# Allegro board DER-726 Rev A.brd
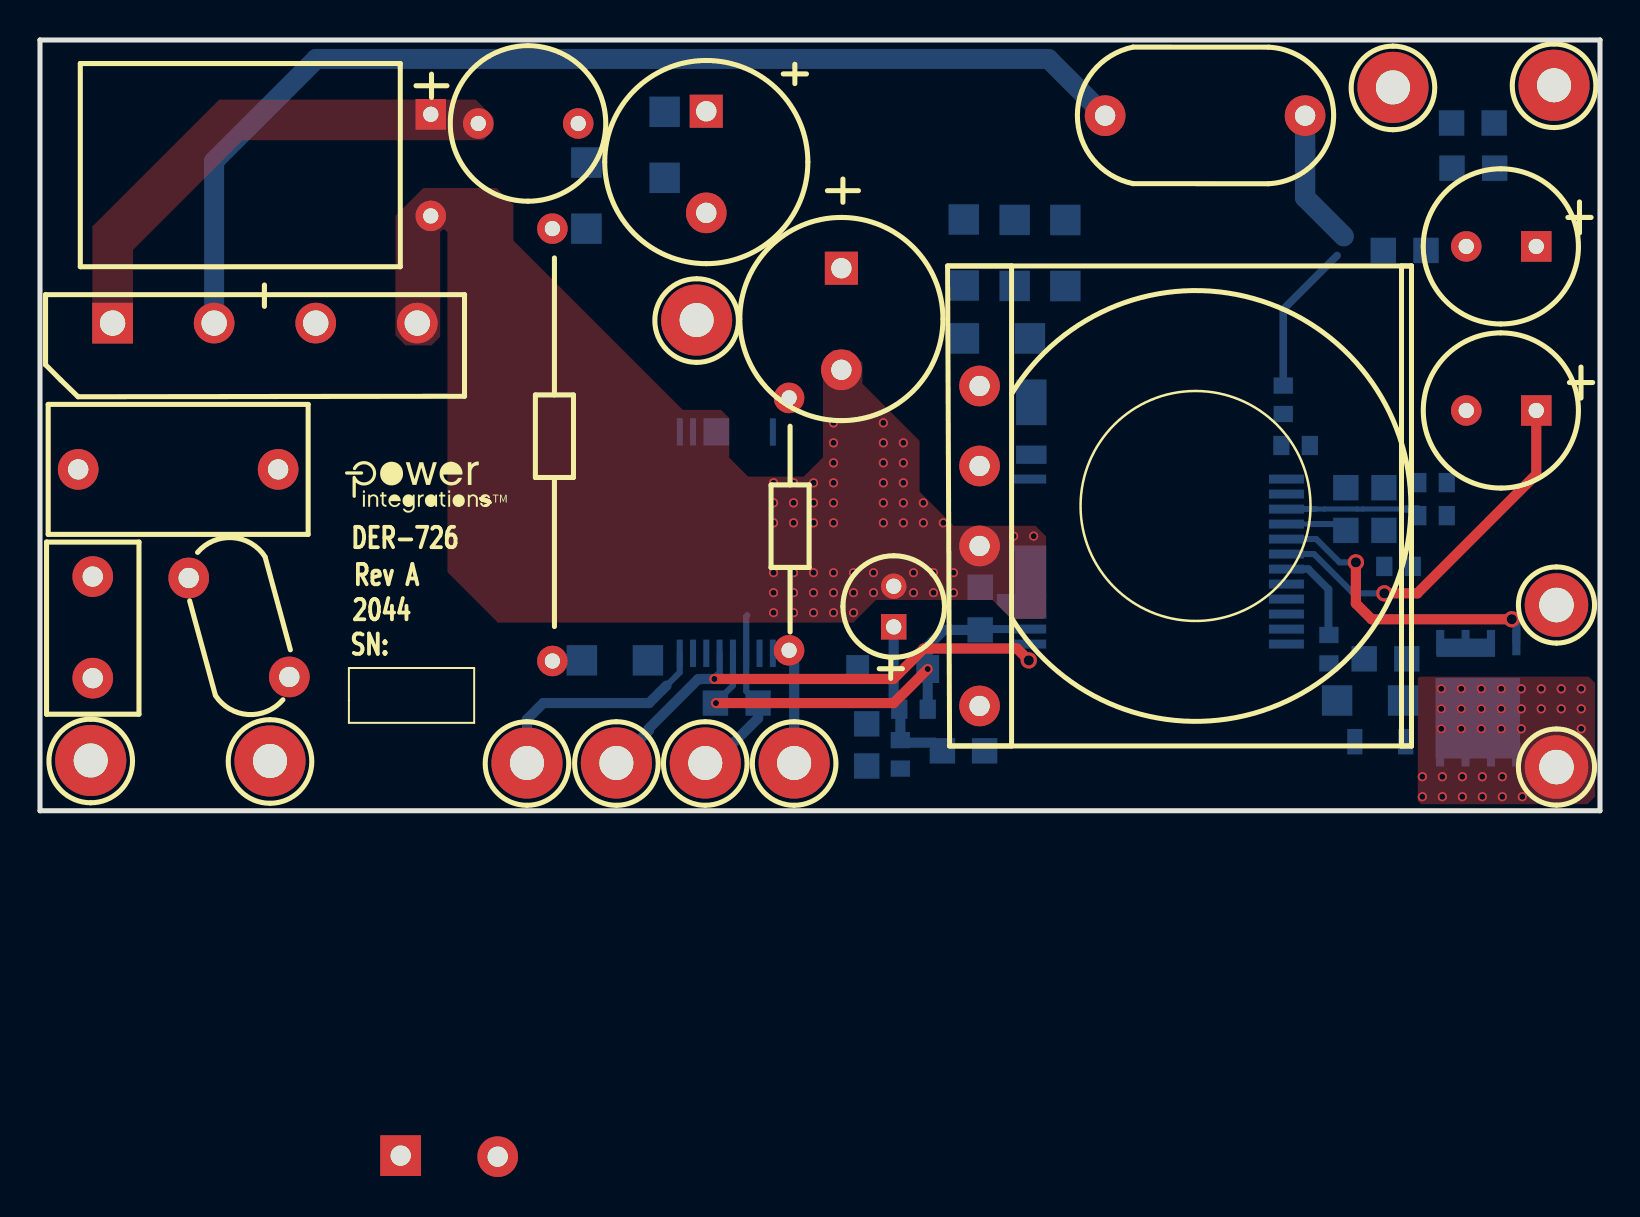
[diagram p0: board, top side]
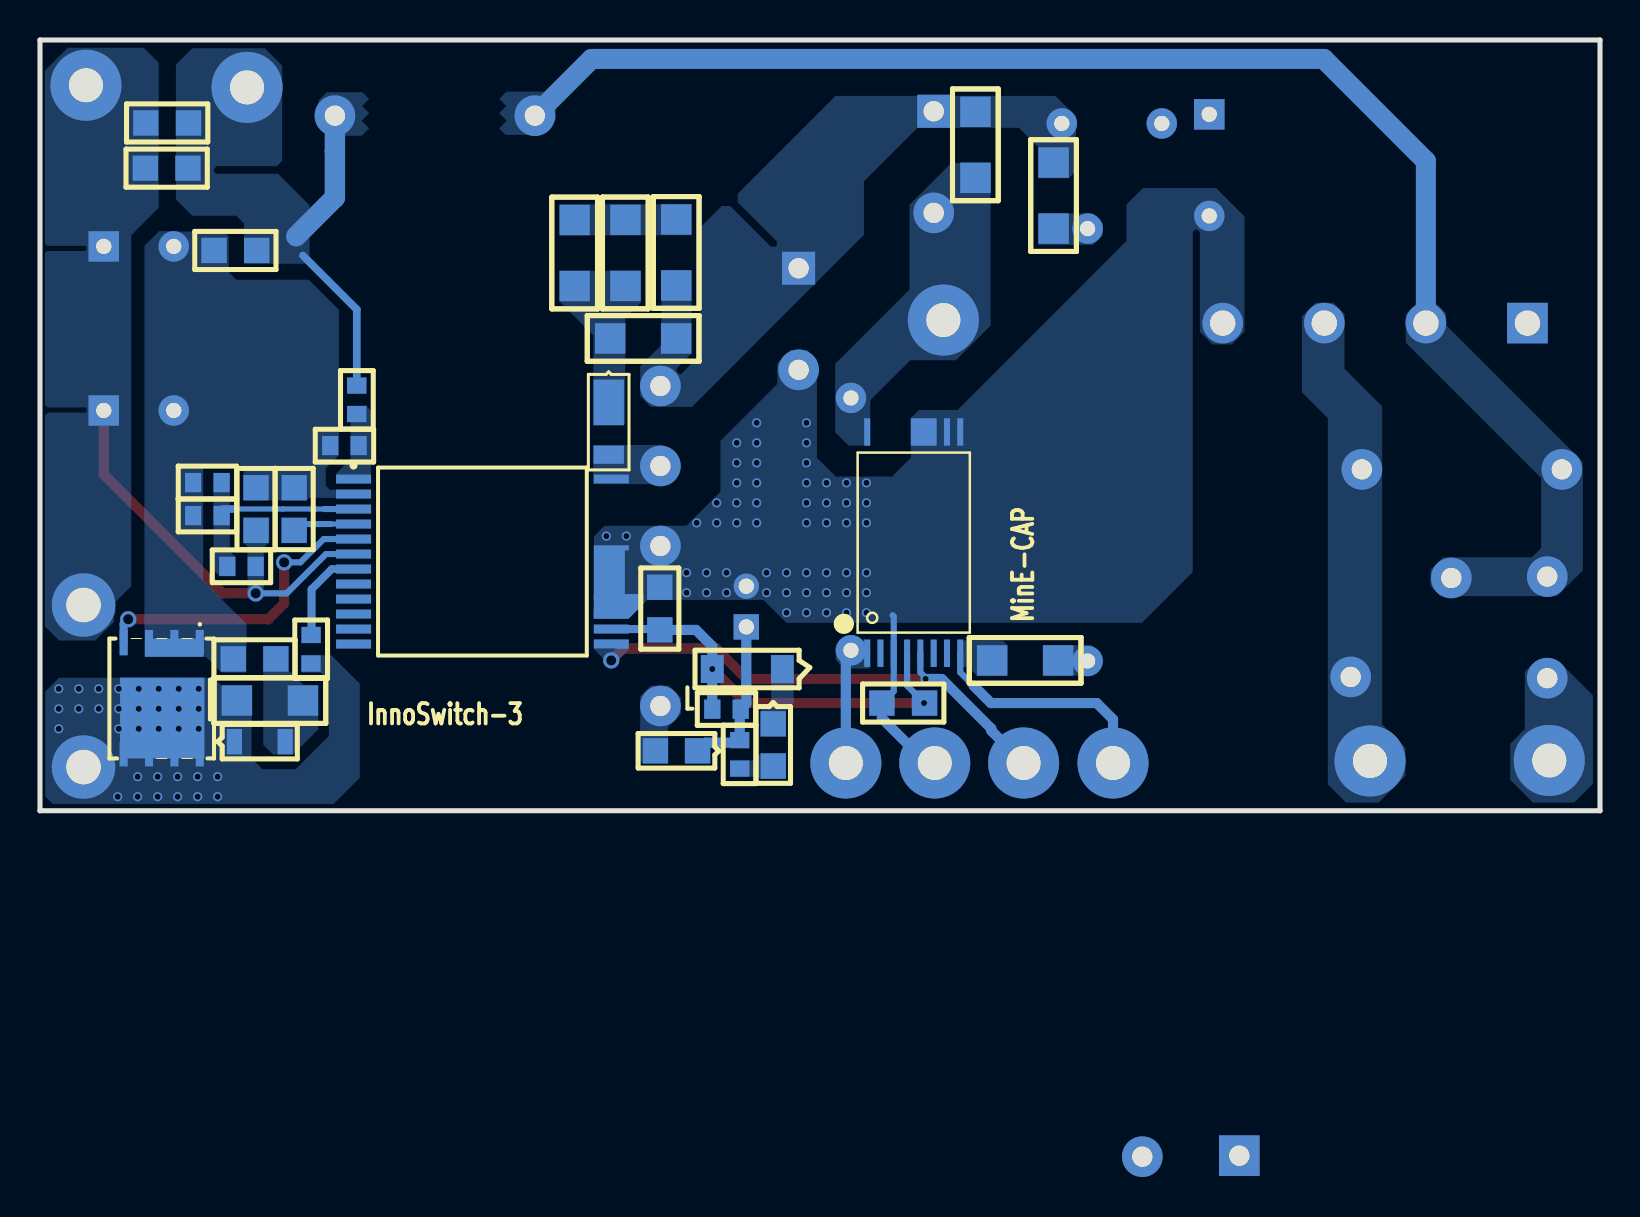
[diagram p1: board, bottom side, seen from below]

Outline 78.02 x 38.54 mm; copper layers: TOP, BOTTOM. Coordinates in mm from the lower left corner of the outline.
Outline path: 0,38.54 78.02,38.54 78.02,0 0,0 0,38.54

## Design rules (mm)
constraint set DEFAULT: min track width 0.508

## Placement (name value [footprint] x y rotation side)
BR1  GBL06  [PIDAXBRIDGEGBL06]  3.63 24.38 0 top
C1  0.1 uF  [PINPXCAPRAD13X7LS10MMD040]  11.91 17.07 180 top
C2  18 uf  [PIPOLCAPCYLD400LS200040]  19.54 34.82 270 top
C3  68 uF  [PIPOLCAPCYLD400LS200040]  33.32 34.98 270 top
C4  33 nF  [PISMC0805]  35.91 5.38 180 bottom
C5  18 uf  [PIPOLCAPCYLD400LS200040]  40.08 27.13 270 top
C6  1000 pF  [PISMC1206]  46.2 26.26 90 bottom
C7  33 uF  [PIPOLCAPCLYD200LS80030]  42.69 9.19 90 top
C8  4.7 uF  [PISMC0805]  47.02 9.04 90 bottom
C9  470 pF  [PINPCAPRAD374X275LS394D040]  53.27 34.76 0 top
C10  1 nF  [PISMC0805]  66.22 7.59 0 bottom
C11  2.2 uF  [PISMC0805]  65.31 16.15 270 bottom
C12  330 uF  [PIPOLCAPCYLD315LS138D030]  74.83 20.02 180 top
C13  1 uF  [PISMC0805]  67.21 16.15 270 bottom
C14  330 uF  [PIPOLCAPCYLD315LS138D030]  74.83 28.22 180 top
C15  330 pF  [PISMC0603]  63.5 18.26 180 bottom
C16  330 pF  [PISMC0603]  68.93 16.41 0 bottom
C18  4.7 uF  [PISMC0805]  72.73 34.39 180 bottom
C19  4.7 uF  [PISMC0805]  72.75 32.13 180 bottom
D  RED  [PITPKEYSTONE125X125]  32.84 24.54 0 top
D1  BAS416,115  [PISMDSOD323]  41.35 4.34 270 bottom
D2  DFLR1800-7  [PISMDDFLR120012]  49.58 20.45 90 bottom
D3  BAV20WS-7-F  [PISMDSOD323]  45.13 3 0 bottom
D4  BAV19WS  [PISMSOD323]  68.3 3.45 180 bottom
F1  3.15 A  [PI_RST_MICROFUSE]  2.64 6.63 90 top
FL1  Hole_70mils  [PI_HOLE_70MIL]  75.84 2.16 0 top
FL2  Hole_70mils  [PI_HOLE_70MIL]  75.84 10.26 0 top
GND  BLK  [PITPKEYSTONE125X125]  67.66 36.17 0 top
L  BLK  [PITPKEYSTONE125X125]  2.54 2.51 0 top
L3  47 uH  [PICHOKETOKINVD345H453LS197D030]  21.92 34.37 0 top
N  WHT  [PITPKEYSTONE125X125]  11.5 2.49 0 top
NOREF  -  []  0 0 90 top
NOREF#2  -  []  -231.6 -144.78 0 top
NOREF#3  -  []  14.7 17.37 0 top
NOREF#4  -  []  0 38.54 0 top
NOREF#5  -  []  -153.78 54.23 0 top
Q1  AONS62922  [PISMPQFN5X6B]  70.03 8.41 0 bottom
R1  3.9 M  [PISMR1206]  31.24 34.95 270 bottom
R2  1 M  [PI18WVRESD80LS100D030]  37.46 20.14 270 top
R3  1.8 M  [PISMR1206]  27.33 32.41 270 bottom
R4  1 M  [PI18WVRESD80LS100D030#2]  25.63 29.11 270 top
R5  1 M  [PISMR1206]  27.1 7.52 0 bottom
R6  3 k  [PISMR0603]  42.97 5.08 0 bottom
R7  47  [PISMR1206]  51.28 29.54 270 bottom
R8  47  [PISMR1206]  48.74 29.54 270 bottom
R9  47  [PISMR0603]  43.02 3.53 270 bottom
R10  390 k  [PISMR1206]  46.2 23.62 0 bottom
R11  47  [PISMR0603]  64.46 7.37 90 bottom
R12  10  [PISMR1206]  68.17 5.51 180 bottom
R13  0.0  [PISMR0603]  62.18 19.84 90 bottom
R14  169 k  [PISMR0603]  67.23 12.22 0 bottom
R15  11.5 k  [PISMR0603]  68.93 14.76 0 bottom
R16  0.009  [PISMR0805]  69.31 28.02 180 bottom
RV1  275 Vac  [PIDISC350X160LS210X140040]  10.87 12.57 285.2 top
S  BLK  [PITPKEYSTONE125X125]  33.27 2.39 0 top
T1  EQ25  [PI_BOBBIN_EQ-25_6P]  57.79 15.24 0 top
U1  MIN1072M  [PI_SM_MINSOP16A_1]  36.65 7.87 180 bottom
U2  INN3679C-H606  [PI_IC_INSOP_24D]  62.34 16.59 180 bottom
V  BLU  [PITPKEYSTONE125X125]  28.83 2.39 0 top
VBOT  WHT  [PITPKEYSTONE125X125]  37.72 2.39 0 top
VO  RED  [PITPKEYSTONE125X125]  75.72 36.28 0 top
VR1  MMSZ5248B-7-F  [PI_SM_SOD-123_12]  40.89 7.09 0 bottom
VTOP  YEL  [PITPKEYSTONE125X125]  24.36 2.39 0 top

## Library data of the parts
BR1 = DISCRETE BRIDGE_+~~-
C1 = CAP NP: alternate symbols: (pinpxcaprad13x7LS10mmD040H)
C2 C5 = CAP POL: alternate symbols: (pipolcapclyd395x630ls200030h)
C3 = CAP POL: alternate symbols: (pipolcapcyld10x20x5mmlsd30h)
C4 C6 C8 C9 C11 C15 C16 C18 C19 = CAP NP
C7 = CAP POL: alternate symbols: (pipolcapclyd200ls80030h)
C10 = CAP NP: alternate symbols: (pismc0805_1); room: 2
C12 C14 = CAP POL: alternate symbols: (pipolcapcyld315ls138d030h); room: 2
C13 = CAP NP: room: 2
D GND L N S V VBOT VO VTOP = TESTPOINT
D1 D3 = DIODE
D2 = DIODE: room: 1
D4 = DIODE: room: 2
F1 = FUSE: alternate symbols: (pirstmicrofusehoz); room: 1
FL1 FL2 = FlyingLead: room: 2
L3 = INDUCTOR: alternate symbols: (pichoketokinvd345h453ls197d030H)
Q1 = FET_N_SGD_123_4_5678: room: 2
R1 R3 R5-R8 R10 R12-R16 = R
R2 R4 = R: alternate symbols: (pi18wresd080ls300d030)
R9 = R: alternate symbols: (pismr0603_1); room: 1
R11 = R: alternate symbols: (pismr0603_1); room: 2
RV1 = VARISTOR: alternate symbols: (pi_disc_354x220_ls220x10_040_h); room: 1
T1 = BEQ25_6P
U1 = MinE-CAP
U2 = Inno3EP_P15
VR1 = DIODE_ZENER

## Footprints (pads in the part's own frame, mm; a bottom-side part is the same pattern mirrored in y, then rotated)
PI18WVRESD80LS100D030
  round 1.524 hole 0.762: 1(-0.5,0) 2(12.12,0)
PI18WVRESD80LS100D030#2
  round 1.524 hole 0.762: 1(0,0) 2(21.62,0)
PI_BOBBIN_EQ-25_6P
  rect 2.032x2.032 hole 1.016: 1(-39.751,-32.487)
  round 2.032 hole 1.016: 2(-10.8,6) 3(-10.8,2) 4(-10.8,-2) 5(-34.9,-32.537) 6(-10.8,-10)
PI_HOLE_70MIL
  round 3.175 hole 1.727: 1(0,0.025)
PI_IC_INSOP_24D
  rect 1.75x0.45 smd: 1(0,0) 2(0,-0.75) 3(0,-1.5) 4(0,-2.25) 5(0,-3) 6(0,-3.75) 7(0,-4.5) 8(0,-5.25) 9(0,-6) 10(0,-6.75) 11(0,-7.5) 12(0,-8.25) 13(12.89,-8.25) 14(12.89,-7.5) 15(12.89,-6.75) 24(12.89,0)
  custom 0.438x0.438 smd: 16(12.89,-4.67)
PI_RST_MICROFUSE
  round 2.032 hole 1.016: 1(0,0) 2(5.08,0)
PI_SM_MINSOP16A_1
  rect 0.3x1.37 smd: 1(0,0) 2(0.665,0) 3(1.33,0) 4(1.995,0) 5(2.66,0) 6(3.325,0) 7(3.99,0) 8(4.655,0) 9(4.655,11.067) 10(3.99,11.067) 16(0,11.067)
  rect 1.292x1.37 smd: 11(2.829,11.067)
PI_SM_SOD-123_12
  rect 1.143x1.397 smd: 1(0,0) 2(3.505,0)
PICHOKETOKINVD345H453LS197D030
  round 1.524 hole 0.762: 1(0,0) 2(5,0)
PIDAXBRIDGEGBL06
  rect 2.032x2.032 hole 1.27: 1(0,0)
  round 2.032 hole 1.27: 2(5.08,0) 3(10.16,0) 4(15.24,0)
PIDISC350X160LS210X140040
  round 2.032 hole 1.016: 1(0,-3.556) 2(6.096,0)
PINPCAPRAD374X275LS394D040
  round 2.032 hole 1.016: 1(0,0) 2(10,0)
PINPXCAPRAD13X7LS10MMD040
  round 2.032 hole 1.016: 1(0,0) 2(10,0)
PIPOLCAPCLYD200LS80030
  rect 1.27x1.27 hole 0.762: 1(0,0)
  round 1.27 hole 0.762: 2(2.032,0)
PIPOLCAPCYLD315LS138D030
  rect 1.524x1.524 hole 0.762: 1(0,0)
  round 1.524 hole 0.762: 2(3.5,0)
PIPOLCAPCYLD400LS200040
  rect 1.651x1.651 hole 1.016: 1(0,0)
  round 2.032 hole 1.016: 2(5.08,0)
PISMC0603
  rect 0.813x0.965 smd: 1(0,0) 2(1.422,0)
PISMC0805
  rect 1.27x1.27 smd: 1(0,0) 2(2.134,0)
PISMC1206
  rect 1.524x1.524 smd: 1(0,0) 2(3.302,0)
PISMDDFLR120012
  rect 2.286x1.524 smd: 1(-0.025,0)
  rect 0.914x1.524 smd: 2(-2.642,0)
PISMDSOD323
  rect 1.27x1.27 smd: 1(0,0) 2(2.108,0)
PISMPQFN5X6B
  rect 0.406x1.27 smd: 1(0,0) 2(1.27,0) 3(2.54,0) 4(3.81,0)
  rect 0.406x1.219 smd: 5(3.81,5.588) 6(2.54,5.588) 7(1.27,5.588) 8(0,5.588)
PISMR0603
  rect 0.813x0.965 smd: 1(0,0) 2(1.422,0)
PISMR0805
  rect 1.27x1.27 smd: 1(0,0) 2(2.134,0)
PISMR1206
  rect 1.524x1.524 smd: 1(0,0) 2(3.302,0)
PISMSOD323
  rect 0.762x1.27 smd: 1(0,0) 2(2.54,0)
PITPKEYSTONE125X125
  round 3.556 hole 1.702: 1(0,0)

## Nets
D: D4.1 FL1.1 Q1.5 Q1.6 Q1.7 Q1.8 R11.1 R12.1
NC8: U2.8
NC9: U2.9
NC10: U2.10
NC11: U2.11
NC12: U2.12
S: C10.2 C11.1 C12.2 C13.1 C14.2 C15.1 C16.2 Q1.1(S) Q1.2 Q1.3 R15.2 R16.1 U2.2
N11525368: BR1.2 C1.2 C9.1 F1.2 RV1.1
N11525664: BR1.3(AC2) C1.1 N.1 RV1.2
N11525782: C3.1 C5.1 C6.1 L3.2 R1.1 R3.1 R10.1 T1.2
N11525810: C9.2 C18.2 C19.2 GND.1 R13.2 R16.2
N11525884: C6.2 R7.1 R8.1
N11526002: D2.1 R7.2 R8.2 R10.2
N11526006: C12.1 C13.2 C14.1 C18.1 C19.1 FL2.1 R14.1 U2.6 VO.1
N11526148: D2.2 T1.3 U2.24
N11526230: BR1.4 C2.2 C4.1 C5.2 C7.2 C8.2 S.1 T1.4 U1.3 U1.9 U1.10 U1.11 U2.16
N11526330: C16.1 R14.2 R15.1 U2.3
N11526430: D3.2 T1.6
N11526456: C10.1 D4.2 R12.2
N11526718: Q1.4 U2.5
N11526838: C7.1 D3.1 R6.1 R9.1
N11527062: D1.2 R9.2
N11527294: C15.2 R13.1 U2.1
N11527492: C4.2 C8.1 R6.2 U1.4 U2.14 VR1.2
N11532941: R3.2 R4.1
N11533086: C3.2 D.1 R1.2 R2.1 U1.16
N11543266: R4.2 R5.1
N11556072: R5.2 U1.8 VTOP.1
N11567872: U1.5 U2.13(VPIN) V.1
N11568750: BR1.1 C2.1 L3.1
N12363198: R2.2 U1.1 VBOT.1
N12366027: C11.2 U2.4
N12367034: F1.1 L.1
N12372611: D1.1 VR1.1
N12385908: R11.2 U2.7

Pads without a net: T1 1 5; U1 2 6 7; U2 15

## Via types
v1: diameter 0.813, hole 0.508, TOP to BOTTOM, 4 vias
v2: diameter 0.457, hole 0.305, TOP to BOTTOM, 90 vias

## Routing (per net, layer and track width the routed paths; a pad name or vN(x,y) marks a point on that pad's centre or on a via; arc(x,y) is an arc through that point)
D:
  vias: v2(69.13,1.7) v2(69.13,0.7) v2(70.08,6.1) v2(70.08,5.1) v2(70.08,4.1) v2(70.13,1.7) v2(70.13,0.7) v2(71.08,6.1) v2(71.08,5.1) v2(71.08,4.1) v2(71.13,1.7) v2(71.13,0.7) v2(72.08,6.1) v2(72.08,5.1) v2(72.08,4.1) v2(72.13,1.7) v2(72.13,0.7) v2(73.08,6.1) v2(73.08,5.1) v2(73.08,4.1) v2(73.13,1.7) v2(73.13,0.7) v2(74.08,6.1) v2(74.08,5.1) v2(74.08,4.1) v2(74.13,0.7) v2(75.08,6.1) v2(75.08,5.1) v2(76.08,6.1) v2(76.08,5.1) v2(77.08,6.1) v2(77.08,5.1) v2(77.08,4.1)
N11525368: length 56
  BOTTOM w1: C9.1 50.43,37.59 13.81,37.59 8.71,32.49 BR1.2
N11525810: length 14.4
  BOTTOM w0.381: R13.2 62.18,25.07 64.87,27.76
  BOTTOM w1.016: C9.2 63.27,32.98 63.27,32.98 63.27,30.66 65.2,28.73
N11526006: length 19
  TOP w0.508: v1(67.23,10.87) 68.88,10.87 74.83,16.82 C12.1
  BOTTOM w0.305: U2.6 63.71,12.84 65.68,10.87 v1(67.23,10.87)
N11526230: length 9
  BOTTOM w0.305: C4.1 35.32,5.98 U1.3 35.32,9.72 35.38,9.78
  BOTTOM w0.508: C4.1 35.91,4.62 33.68,2.39 S.1
  vias: v2(36.69,16.4) v2(36.69,15.4) v2(36.69,14.4) v2(36.69,11.9) v2(36.69,10.9) v2(36.69,9.9) v2(37.69,16.4) v2(37.69,15.4) v2(37.69,14.4) v2(37.69,11.9) v2(37.69,10.9) v2(37.69,9.9) v2(38.69,16.4) v2(38.69,15.4) v2(38.69,14.4) v2(38.69,11.9) v2(38.69,10.9) v2(38.69,9.9) v2(39.69,19.4) v2(39.69,18.4) v2(39.69,17.4) v2(39.69,16.4) v2(39.69,15.4) v2(39.69,14.4) v2(39.69,11.9) v2(39.69,10.9) v2(39.69,9.9) v2(40.69,11.9) v2(40.69,10.9) v2(40.69,9.9) v2(41.69,11.9) v2(41.69,10.9) v2(42.18,19.4) v2(42.18,18.4) v2(42.18,17.4) v2(42.18,16.4) v2(42.18,15.4) v2(42.18,14.4) v2(43.18,18.4) v2(43.18,17.4) v2(43.18,16.4) v2(43.18,15.4) v2(43.18,14.4) v2(43.69,11.9) v2(43.69,10.9) v2(44.18,15.4) v2(44.18,14.4) v2(44.69,11.9) v2(44.69,10.9) v2(45.18,14.4) v2(45.69,11.9) v2(45.69,10.9) v2(48.69,13.73) v2(49.69,13.73)
N11526330: length 6.6
  BOTTOM w0.254: 68.33,15.09 66.14,15.09 66.14,15.09 65.87,15.09 65.87,15.09 64.24,15.09 64.24,15.09 63.77,15.09
  BOTTOM w0.305: 63.77,15.09 U2.3
  BOTTOM w0.381: 68.91,15.09 68.33,15.09
N11526718: length 15.4
  TOP w0.508: v1(65.81,12.42) 65.81,10.36 66.6,9.58 v1(73.61,9.58)
  BOTTOM w0.305: U2.5 63.83,13.59 64.99,12.42 v1(65.81,12.42)
  BOTTOM w0.4: Q1.4 73.84,9.35 v1(73.61,9.58)
N11526838: length 8.1
  BOTTOM w0.508: D3.1 44.73,3.4 43.15,3.4 R9.1 43.02,5.03 R6.1 42.69,5.36 C7.1
N11527492: length 22.7
  TOP w0.508: v2(33.8,5.38) 42.69,5.38 v2(44.4,7.09)
  BOTTOM w0.305: v2(33.8,5.38) C4.2 34.65,6.26 U1.4
  BOTTOM w0.4: U2.14 47.06,9.09 C8.1
  BOTTOM w0.508: R6.2 v2(44.4,7.09) 44.4,8.23 45.21,9.04 C8.1
N11556072: length 11.8
  BOTTOM w0.305: U1.8 31.99,6.92 31.33,6.26
  BOTTOM w0.508: 31.33,6.26 30.46,5.38 25.17,5.38 24.36,4.57 VTOP.1
N11567872: length 24.7
  TOP w0.508: v2(33.73,6.59) 42.68,6.59 44.2,8.11 48.86,8.11 v1(49.45,7.52)
  BOTTOM w0.305: U1.5 33.99,6.92 33.73,6.65 v2(33.73,6.59)
  BOTTOM w0.508: V.1 30.44,4 30.44,4.11 32.91,6.58 33.02,6.58 33.03,6.59 v2(33.73,6.59)
N12363198: length 5.6
  BOTTOM w0.508: VBOT.1 37.72,7.62 37.46,7.87
N12366027: length 3.1
  BOTTOM w0.254: U2.4 63.48,14.34
  BOTTOM w0.305: 63.48,14.34 64.99,14.34 C11.2
N12385908: length 4.8
  BOTTOM w0.381: U2.7 63.43,12.09 64.44,11.07
  BOTTOM w0.4: R11.2 64.44,8.81 64.44,11.07

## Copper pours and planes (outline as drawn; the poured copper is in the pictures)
D on BOTTOM (solid shape): 74.01,2.62 69.8,2.62 69.8,6.65 74.01,6.65
D on TOP: 69.06,0.33 77.39,0.33 77.77,0.71 77.77,6.4 77.47,6.71 68.98,6.71 68.91,6.63 68.91,0.48
D on BOTTOM: 77.75,0.71 77.75,5.97 77.06,6.65 69.34,6.65 68.91,6.22 67.43,6.22 67.43,2.62 66.9,2.08 65.22,2.08 63.57,3.73 63.57,6.5 63.98,6.91 64.92,6.91 64.95,6.93 64.95,7.75 64.92,7.77 63.45,7.77 62.02,6.35 62.02,1.65 63.33,0.34 77.38,0.34
S on BOTTOM (solid shape): 72.77,7.7 69.85,7.7 69.85,8.61 72.77,8.61
S on BOTTOM: 63.07,17.78 63.73,17.12 63.73,16.26 63.53,16.05 61.47,16.05 61.47,15.65 64.54,15.65 64.67,15.52 67.84,15.52 67.84,17.12 68.09,17.37 69.64,17.37 69.86,17.16 69.86,11.51 67.69,9.34 67.69,6.91 68.93,6.91 69.72,7.7 72.79,7.7 72.79,28.24 72.06,28.98 71.16,28.98 71.14,28.96 68.83,28.96 68.58,28.7 68.58,26.92 68.21,26.56 64.58,26.56 63.07,25.05
N11525368 on BOTTOM: 52.86,35.96 54.68,35.96 55.05,35.6 54.7,35.24 55.05,34.88 54.67,34.5 55.05,34.12 54.72,33.79 52.97,33.79 52.22,34.54 52.22,35.33 52.84,35.95
N11525368 on BOTTOM: 8.48,12.04 7.85,12.67 3.4,12.67 2.94,13.13 2.94,16.64 9.71,23.41 9.71,24.83 9.17,25.37 8.2,25.37 7.69,24.87 7.69,24.28 0.86,17.45 0.86,12.01 2.14,10.73 7.99,10.73 8.48,11.23
N11525664 on BOTTOM: 13.61,19.63 14.91,20.93 14.91,24.71 14.22,25.4 13.33,25.4 12.77,24.84 12.77,22.1 10.89,20.22 10.89,4.32 9.73,3.15 9.73,1.75 11.07,0.41 12.7,0.41 13.61,1.32
N11525782 on BOTTOM: 46.91,27.03 46.94,27 46.94,23.29 48,22.23 48,20.73 47.47,20.19 45.41,20.19 36.81,28.79 36.81,31.47 34.13,34.15 29.07,34.15 28.09,33.17 28.09,31.62 26.57,31.62 26.21,31.98 26.21,34.72 27.23,35.74 38.23,35.74 43.13,30.85 43.13,30.43 41.17,28.47 41.17,28.27 41.23,28.21 41.46,28.21 43.49,30.24 43.93,30.24 44.98,29.18 44.98,22.81 45.95,21.84 46.05,21.84 46.17,21.97 46.17,22.12 45.44,22.86 45.44,27.03
N11525810 on BOTTOM: 69.31,31.95 69.31,32.11 69.19,32.23 66.16,32.23 65.91,32.49 65.91,37.26 66.77,38.13 70.41,38.13 71.22,37.31 71.22,30.57 70.41,29.75 68.21,29.75 67.82,29.36 67.82,27.38 67.79,27.36 64.74,27.36 64.54,27.56 64.54,30.28 66.11,31.85 69.21,31.85
N11525810 on BOTTOM: 63.63,33.75 61.92,33.75 61.55,34.12 61.94,34.5 61.55,34.88 61.91,35.24 61.55,35.6 61.88,35.93 63.67,35.93 64.09,35.5 64.09,34.21 64.09,34.21
N11525884 on BOTTOM: 45.42,30.33 45.42,28.78 52.02,28.78 52.02,30.33
N11526002 on BOTTOM: 48.82,19.28 50.34,19.28 50.34,23.77 52.02,25.45 52.02,27 47.96,27 47.96,25.43 48.74,24.64 48.74,19.35
N11526006 on BOTTOM: 72.82,38.15 76.63,38.15 77.77,37.01 77.77,28.37 77.65,28.24 75.77,28.24 75.69,28.17 75.69,28.07 75.77,27.99 77.67,27.99 77.77,27.89 77.77,20.29 77.65,20.17 75.74,20.17 75.69,20.12 75.69,19.96 75.74,19.91 77.62,19.91 77.77,19.76 77.77,9.22 77.06,8.51 75.26,8.51 74.24,9.53 74.24,10.44 73.45,11.23 73.45,28.78 72.08,30.15 72.08,37.41
N11526006 on BOTTOM: 67.84,14.66 67.84,13.41 67.64,13.21 67.64,10.72 67.38,10.46 67.05,10.46 66.82,10.69 66.82,13.16 66.55,13.44 66.55,14.66
N11526148 on BOTTOM: 50.35,18.29 46.89,18.29 46.33,17.73 46.33,16.84 46.82,16.36 46.82,16.33 50.35,16.33
N11526230 on BOTTOM (solid shape): 50.32,9.61 48.57,9.61 47.85,10.33 47.85,10.83 50.32,10.83
N11526230 on TOP: 45.69,14.25 49.78,14.25 50.31,13.72 50.31,9.73 50.19,9.6 48.56,9.6 47.62,10.54 41.81,10.54 40.66,9.4 22.91,9.4 20.37,11.94 20.37,28.93 20.24,29.06 20.14,29.06 20.01,28.93 20.01,23.7 19.58,23.27 18.29,23.27 17.78,23.77 17.78,29.74 19.17,31.14 22.83,31.14 23.67,30.3 23.67,28.52 32.15,20.04 34.06,20.04 34.47,19.63 34.47,17.65 35.4,16.71 38.2,16.71 39.16,17.68 39.16,22.56 39.65,23.04 40.48,23.04 41.13,22.39 41.13,21.35 43.99,18.49 43.99,15.95
N11526230 on BOTTOM: 45.69,14.25 43.99,15.95 43.99,18.49 41.15,21.34 41.15,22.38 40.48,23.04 39.65,23.04 39.16,22.56 39.16,17.65 38.22,16.71 35.4,16.71 34.47,17.65 34.47,19.63 34.06,20.04 32.13,20.04 23.68,28.49 23.68,30.31 22.86,31.14 19.2,31.14 17.78,29.72 17.78,23.95 18.41,23.32 19.38,23.32 20.01,23.95 20.01,28.93 20.14,29.06 20.24,29.06 20.37,28.93 20.37,11.94 22.91,9.4 40.69,9.4 41.83,10.54 47.65,10.54 47.88,10.31 50.11,10.31 50.31,10.52 50.31,13.72 49.78,14.25
N11526330 on BOTTOM: 68.53,16.89 68.53,12.98 68.25,12.7 68.25,11.73 69.03,11.73 69.34,12.04 69.34,16.89
N11526430 on BOTTOM: 46.56,6.25 47.47,6.25 48,5.71 48,2.49 47.88,2.36 46.61,2.36 46.61,4.19 45.97,4.83 45.97,5.66
N11526456 on BOTTOM: 66.85,8.23 65.66,8.23 65.58,8.15 65.58,7.01 65.5,6.93 65.48,6.93 64.82,6.27 64.11,6.27 64.11,4.06 65.35,2.82 66.37,2.82 66.85,3.3
N11527062 on BOTTOM: 40.71,2.87 40.71,1.6 41.98,1.6 42.09,1.7 43.51,1.7 43.51,2.51 42.34,2.51 41.98,2.87
N11527294 on BOTTOM: 61.47,16.36 63.15,16.36 63.2,16.41 63.2,16.87 62.61,17.45 62.61,17.48 62.48,17.61 62.48,20.24 61.69,20.24 61.47,20.02
N11532941 on BOTTOM: 24.86,29.39 24.86,28.78 25.35,28.3 28.09,28.3 28.09,29.87 25.35,29.87
N11533086 on BOTTOM: 38.25,22.35 38.25,18.92 37.59,18.26 36.5,18.26 36.5,20.52 34.49,22.53 32.2,22.53 30.48,24.26 30.48,32.38 32.45,32.38 34.53,30.3 34.53,26.07
N11543266 on BOTTOM: 27.86,8.28 27.86,6.76 25.42,6.76 24.91,7.26 24.91,7.75 25.45,8.28
N11556072 on BOTTOM: 32.08,8.51 32.08,7.19 31.59,7.19 31.16,6.76 29.64,6.76 29.64,8.28 29.87,8.51
N11567872 on BOTTOM: 48.59,8.56 50.31,8.56 50.31,8.08 49.63,7.39 49.25,7.39 48.59,8.05
N11568750 on TOP: 4.65,28.04 10.13,33.53 22.17,33.53 22.68,34.04 22.68,34.67 21.79,35.56 8.96,35.56 2.61,29.21 2.61,23.37 4.65,23.37
N12363198 on BOTTOM: 36.5,8.56 36.5,7.19 36.57,7.11 37.79,7.11 38.22,7.54 38.22,8.2 37.87,8.56
N12367034 on BOTTOM: 3.76,6.96 3.76,4.09 4.49,3.35 4.49,1.55 3.35,0.41 1.29,0.41 0.35,1.35 0.35,5.77 2.05,7.47 3.25,7.47
N12372611 on BOTTOM: 40.71,3.71 41.98,3.71 41.98,4.98 41.45,5.51 41.45,7.77 40.33,7.77 40.33,5.41 40.71,5.03

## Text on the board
Ref Des/Silkscreen Bottom: InnoSwitch-3 | MinE-CAP
Ref Des/Silkscreen Top: SN: | DER-726 | 2044 | Rev A
User.6: 14.  FAB HOUSE LOGO,DATE CODE TO BE IN SILK SCREEN ONLY.DO NOT USE COPPER. | 13.  MATERIAL FR4 COPPER 2oz THICKNESS 0.062"
User.8: FIGURE | FINISHED_SIZE | 12.0 | 20.0 | 30.0 | 40.0 | 50.0 | 67.0 | 68.0 | DRILL CHART: TOP to BOTTOM | ALL UNITS ARE IN MILS | TOLERANCE_DRILL | +3.0/-3.0 | PLATED | QTY | 90 | 4 | 14 | 18 | 9 | 2
